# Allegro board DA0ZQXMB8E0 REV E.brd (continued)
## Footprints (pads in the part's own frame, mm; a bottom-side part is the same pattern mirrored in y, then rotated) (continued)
BGA1168-INTEL-HASWELL
  round 0.508 smd: A3(18.177,-11.314) A62(-18.722,-11.314) AW1(19.314,10.727) AY2(18.771,11.314) C1(19.314,-10.177)
  round 0.381 smd: A4(17.421,-11.314) AF9(14.282,3.12) AH28(2.793,3.975) AH42(-6.31,3.975) AH44(-7.611,3.975) AH46(-8.911,3.975) AJ43(-6.96,4.3) AJ45(-8.261,4.3) AJ47(-9.561,4.3) AT1(19.314,8.683) AU1(19.314,9.343) AV1(19.314,10.004) AV2(18.654,9.993) AW2(18.654,10.654) AW3(17.993,10.654) AY3(18.047,11.314) AY4(17.387,11.314) AY5(16.726,11.314) E23(5.981,-8.713) E25(4.6,-8.713) E27(3.474,-8.713) E43(-6.556,-8.713) E45(-7.937,-8.713) E47(-9.064,-8.713) E63(-19.314,-8.667) F1(19.314,-7.878) F22(6.597,-8.256) F24(5.291,-8.188) F26(4.037,-8.188) F28(2.783,-8.188) F42(-5.993,-8.188) F46(-8.5,-8.188) F48(-9.754,-8.188) G22(6.707,-7.546) G23(5.981,-7.863) G25(4.6,-7.863) G27(3.474,-7.863) G43(-6.556,-7.863) G45(-7.937,-7.863) G47(-9.064,-7.863) H22(6.707,-6.734) H23(6.199,-7.14) J22(6.707,-5.921) J23(6.199,-6.327)
  round 0.305 smd: A23(6.128,-11.314) A24(5.291,-10.989) A25(4.6,-11.314) A27(3.474,-11.314) A28(2.783,-10.989) A36(-2.232,-10.989) A44(-7.247,-10.989) A47(-9.064,-11.314) AA1(19.314,0.402) AA2(18.664,0.402) AA61(-18.014,0.324) AA62(-18.664,0.362) AA63(-19.314,0.362) AC1(19.314,1.152) AC2(18.664,1.152) AC61(-18.014,1.15) AC62(-18.664,1.112) AC63(-19.314,1.112) AD1(19.314,1.901) AD2(18.664,1.901) AD6(16.027,1.691) AD61(-18.014,1.823) AD62(-18.664,1.861) AD63(-19.314,1.861) AE5(16.678,2.643) AE7(15.377,2.643) AE8(14.727,2.643) AF1(19.314,2.65) AF2(18.664,2.65) AG1(19.314,3.4) AG2(18.664,3.4) AH1(19.314,4.149) AH2(18.664,4.149) AK2(18.664,4.898) AK61(-18.014,5.209) AK62(-18.664,5.315) AK63(-19.314,5.315) AL1(19.314,5.647) AL2(18.664,5.647) AL17(10.092,5.268) AL26(3.858,5.602) AL28(2.905,5.602) AL43(-6.582,5.602) AL45(-7.56,5.602) AL46(-8.487,5.602) AL48(-9.542,5.602) AM1(19.314,6.397) AM2(18.664,6.397) AM3(18.014,6.359) AM29(1.953,6.252) AM32(0.49,6.252) AM36(-2.266,6.252) AM38(-3.32,6.252) AM40(-4.817,6.252) AM42(-5.63,6.252) AM43(-6.582,6.252) AM45(-7.56,6.252) AM46(-8.487,6.252) AM48(-9.542,6.252) AM52(-12.269,6.252) AM54(-13.295,6.252) AN1(19.314,7.146) AN2(18.664,7.146) AN36(-2.266,6.903) AN38(-3.32,6.903) AN39(-4.228,6.578) AN40(-4.817,6.903) AN42(-5.63,6.903) AN43(-6.582,6.903) AN45(-7.56,6.903) AN46(-8.487,6.903) AP1(19.314,7.895) AP2(18.664,7.895) AP8(15.011,7.738) AP36(-2.266,7.553) AP38(-3.32,7.553) AP39(-4.228,7.228) AP45(-7.56,7.553) AR5(16.413,8.063) AR8(15.011,8.388) AR15(11.174,8.388) AR42(-5.63,8.203) AR45(-7.56,8.203) AR46(-8.487,8.203) AR48(-9.542,8.203) AT2(18.664,8.645) AT3(18.014,8.683) AT4(17.363,8.683) AT7(15.575,8.713) AT10(13.657,8.713) AT13(11.738,8.713) AT43(-7.422,8.905) AT46(-8.996,8.905) AU2(18.659,9.333) AU3(17.999,9.333) AU4(17.338,9.333) AU6(15.977,9.363) AU8(14.478,9.363) AU12(12.154,9.363) AU42(-6.309,9.363) AU43(-6.959,9.363) AU44(-7.884,9.363) AU46(-8.534,9.363) AU47(-9.459,9.363) AV3(17.993,9.993) AV4(17.338,9.993) AV5(16.65,10.014) AV6(15.977,10.014) AV7(15.151,10.014) AV8(14.478,10.014) AV10(13.653,10.014) AV11(12.98,10.014) AV42(-6.26,10.014) AV43(-7.009,10.014) AV44(-7.834,10.014) AW4(17.338,10.654) AW5(16.688,10.664) AW6(15.939,10.664) AW7(15.189,10.664) AW8(14.44,10.664) AW11(12.942,10.664) AW12(12.192,10.664) AW23(5.672,10.664) AW25(4.321,10.664) AW29(1.89,10.664) AW30(1.214,10.339) AW31(0.539,10.664) AW33(-0.137,10.339) AW34(-0.71,10.664) AW37(-3.11,10.664) AW39(-3.859,10.664) AW41(-5.434,10.664) AW42(-6.26,10.664) AW43(-7.009,10.664) AW49(-10.158,10.664) AW50(-10.984,10.664) AW51(-11.666,10.339) AW53(-13.017,10.339) AW54(-13.693,10.664) AY6(15.939,11.314) AY7(15.189,11.314) AY8(14.44,11.314) AY26(3.645,10.989) AY33(-0.137,10.989) AY40(-4.685,11.314) AY41(-5.434,11.314) AY49(-10.158,11.314) B23(5.864,-10.672) B24(5.291,-10.339) B25(4.6,-10.664) B26(4.037,-10.339) B27(3.474,-10.664) B28(2.783,-10.339) B37(-2.922,-10.664) B43(-6.556,-10.664) C21(7.423,-9.529) C24(5.263,-9.282) C25(4.6,-10.014) C26(4.037,-9.689) C27(3.474,-10.014) C28(2.756,-9.282) C31(0.966,-10.014) C33(-0.415,-10.014) C37(-2.922,-10.014) C39(-4.049,-10.014) C41(-5.43,-10.014) C42(-5.993,-9.689) C45(-7.937,-10.014) C46(-8.5,-9.689) C47(-9.064,-10.014) C48(-9.756,-9.282) D2(18.664,-9.24) D3(18.014,-9.278) D5(16.636,-9.472) D6(15.945,-9.529) D8(15.157,-9.529) D9(14.37,-9.529) D17(10.001,-9.529) D18(9.214,-9.529) D20(8.306,-9.529) D21(7.079,-8.891) D23(5.937,-9.529) D25(4.6,-9.363) D26(4.037,-9.038) D27(3.474,-9.363) D43(-6.556,-9.363) D47(-9.064,-9.363) E2(18.664,-8.589) E3(18.014,-8.627) E4(17.363,-8.627) E5(16.712,-8.695) E6(15.76,-8.695) E17(10.045,-8.695) E18(9.092,-8.695) E20(8.14,-8.695) F2(18.664,-7.84) F3(18.014,-7.802) F4(17.363,-7.802) F8(14.807,-8.045) F17(10.045,-8.045) F18(9.092,-8.045) F62(-18.664,-7.88) G3(18.014,-7.129) G4(17.363,-7.129) G5(16.712,-7.395) G6(15.76,-7.395) G8(14.807,-7.395) H5(16.712,-6.745) H6(15.76,-6.745) H8(14.807,-6.745) J3(18.014,-6.303) J4(17.363,-6.303) J5(16.687,-6.094) J6(15.747,-6.094) J8(14.807,-6.094) J11(12.902,-6.094) K1(19.314,-5.592) K2(18.664,-5.592) K61(-18.014,-5.67) K62(-18.664,-5.632) K63(-19.314,-5.632) L1(19.314,-4.843) L2(18.664,-4.843) L6(16.027,-4.977) L8(14.727,-4.977) L61(-18.014,-4.845) L62(-18.664,-4.883) L63(-19.314,-4.883) N1(19.314,-4.093) N2(18.664,-4.093) N3(18.014,-4.132) N4(17.363,-4.132) N5(16.678,-4.024) N6(16.027,-4.024) N7(15.377,-4.024) N8(14.727,-4.024) N61(-18.014,-4.172) N62(-18.664,-4.134) N63(-19.314,-4.134) P1(19.314,-3.344) P2(18.664,-3.344) P3(18.014,-3.306) P4(17.363,-3.306) P61(-18.014,-3.346) P62(-18.664,-3.384) P63(-19.314,-3.384) R5(16.678,-3.072) R6(16.027,-3.072) R7(15.377,-3.072) R8(14.727,-3.072) T1(19.314,-2.595) T2(18.664,-2.595) T3(18.014,-2.633) T4(17.363,-2.633) T61(-18.014,-2.673) T62(-18.664,-2.635) T63(-19.314,-2.635) U1(19.314,-1.846) U2(18.664,-1.846) U5(16.678,-2.119) U6(16.027,-2.119) U7(15.377,-2.119) U8(14.727,-2.119) U61(-18.014,-1.848) U62(-18.664,-1.886) U63(-19.314,-1.886) V1(19.314,-1.096) V2(18.664,-1.096) Y1(19.314,-0.347) Y2(18.664,-0.347) Y61(-18.014,-0.349) Y62(-18.664,-0.387) Y63(-19.314,-0.387)
  round 0.33 smd: AK23(5.786,4.952) AK25(4.81,4.952) AK26(3.858,4.952) AK28(2.905,4.952) AK43(-6.582,4.952) AK45(-7.56,4.952) AK46(-8.462,4.952) AK48(-9.516,4.952)
BSH-030-01-L-D-A-TR-60P-LDH
  round 1.016 hole 1.016 unplated: (-10.063,-2.666) (10.063,-2.666)
  rect 0.279x2.261 smd: 1(-7.25,-2.864) 2(-6.75,-2.864) 3(-6.25,-2.864) 4(-5.75,-2.864) 5(-5.25,-2.864) 6(-4.75,-2.864) 7(-4.25,-2.864) 8(-3.75,-2.864) 9(-3.25,-2.864) 10(-2.75,-2.864) 11(-2.25,-2.864) 12(-1.75,-2.864) 13(-1.25,-2.864) 14(-0.75,-2.864) 15(-0.25,-2.864) 16(0.25,-2.864) 17(0.75,-2.864) 18(1.25,-2.864) 19(1.75,-2.864) 20(2.25,-2.864) 21(2.75,-2.864) 22(3.25,-2.864) 23(3.75,-2.864) 24(4.25,-2.864) 25(4.75,-2.864) 26(5.25,-2.864) 27(5.75,-2.864) 28(6.25,-2.864) 29(6.75,-2.864) 30(7.25,-2.864) 31(7.25,2.864) 34(5.75,2.864) 36(4.75,2.864) 38(3.75,2.864) 39(3.25,2.864) 40(2.75,2.864) 41(2.25,2.864) 42(1.75,2.864) 43(1.25,2.864) 44(0.75,2.864) 45(0.25,2.864) 46(-0.25,2.864) 47(-0.75,2.864) 48(-1.25,2.864) 49(-1.75,2.864) 50(-2.25,2.864) 51(-2.75,2.864) 52(-3.25,2.864) 53(-3.75,2.864) 54(-4.25,2.864) 55(-4.75,2.864) 56(-5.25,2.864) 57(-5.75,2.864) 58(-6.25,2.864) 59(-6.75,2.864) 60(-7.25,2.864)
CC0402
  custom 0.12x0.12 smd: 1(0.39,0) 2(-0.39,0)
CC0603#2
  rect 0.813x0.711 smd: 1(0.737,0) 2(-0.737,0)
CC0805
  rect 0.94x1.346 smd: 2(-0.895,0)
CC1206
  rect 1.6x1.6 smd: 1(1.702,0) 2(-1.702,0)
CC1808
  rect 2.159x2.286 smd: 1(-2.349,0) 2(2.349,0)
CC3528
  rect 2.032x2.413 smd: 1(1.6,0) 2(-1.6,0)
CC7343
  rect 2.413x2.819 smd: 1(-3.2,0) 2(3.2,0)
CHOKE-PCMC063T-3R3MN-SMT#2
  rect 1.854x3.505 smd: 1(-3.275,0) 2(3.275,0)
CHOKE-PCMC063T-R82MN-4P-SMT
  custom 0.591x0.591 smd: 1(-3.596,0) 2(3.596,0)
  rect 1.473x0.305 smd: 3(-2.452,0) 4(2.452,0)
D-DO-214AC
  rect 1.88x2.032 smd: 1(-2.1,0)
DDR-C-2013289-204P
  round 1.6 hole 1.6 unplated: (-33.4,0)
  round 1.092 hole 1.092 unplated: (33.4,0)
  rect 0.356x2.007 smd: 1(-31.65,-4.1) 3(-31.05,-4.1) 4(-30.75,4.1) 5(-30.45,-4.1) 7(-29.85,-4.1) 8(-29.55,4.1) 9(-29.25,-4.1) 11(-28.65,-4.1) 13(-28.05,-4.1) 15(-27.45,-4.1) 17(-26.85,-4.1) 19(-26.25,-4.1) 21(-25.65,-4.1) 23(-25.05,-4.1) 31(-22.65,-4.1) 37(-20.85,-4.1) 41(-19.65,-4.1) 43(-19.05,-4.1) 49(-17.25,-4.1) 51(-16.65,-4.1) 53(-16.05,-4.1) 55(-15.45,-4.1) 59(-14.25,-4.1) 74(-7.35,4.1) 76(-6.75,4.1) 78(-6.15,4.1) 80(-5.55,4.1) 82(-4.95,4.1) 84(-4.35,4.1) 86(-3.75,4.1) 88(-3.15,4.1) 90(-2.55,4.1) 92(-1.95,4.1) 96(-0.75,4.1) 98(-0.15,4.1) 100(0.45,4.1) 102(1.05,4.1) 104(1.65,4.1) 106(2.25,4.1) 108(2.85,4.1) 110(3.45,4.1) 112(4.05,4.1) 114(4.65,4.1) 116(5.25,4.1) 118(5.85,4.1) 120(6.45,4.1) 122(7.05,4.1) 124(7.65,4.1) 126(8.25,4.1) 128(8.85,4.1) 130(9.45,4.1) 132(10.05,4.1) 134(10.65,4.1) 136(11.25,4.1) 138(11.85,4.1) 140(12.45,4.1) 142(13.05,4.1) 144(13.65,4.1) 148(14.85,4.1) 150(15.45,4.1) 152(16.05,4.1) 154(16.65,4.1) 156(17.25,4.1) 157(17.55,-4.1) 159(18.15,-4.1) 161(18.75,-4.1) 163(19.35,-4.1) 164(19.65,4.1) 165(19.95,-4.1) 166(20.25,4.1) 167(20.55,-4.1) 168(20.85,4.1) 171(21.75,-4.1) 173(22.35,-4.1) 175(22.95,-4.1) 176(23.25,4.1) 177(23.55,-4.1) 178(23.85,4.1) 179(24.15,-4.1) 181(24.75,-4.1) 183(25.35,-4.1) 184(25.65,4.1) 185(25.95,-4.1) 186(26.25,4.1) 187(26.55,-4.1) 189(27.15,-4.1) 191(27.75,-4.1) 193(28.35,-4.1) 195(28.95,-4.1) 196(29.25,4.1) 197(29.55,-4.1) 198(29.85,4.1) 199(30.15,-4.1) 200(30.45,4.1) 201(30.75,-4.1) 202(31.05,4.1) 203(31.35,-4.1) 204(31.65,4.1)
  rect 3.505x4.597 smd: 205(-32.8,12) 206(32.8,12)
DSM
  rect 1.016x0.508 smd: 1(-1.3,0) 2(1.321,0)
DSMV
  rect 1.016x0.762 smd: 1(-1.27,0) 2(1.27,0)
GS12401-1011-40P-R-NH-SMT
  round 0.94 hole 0.94 unplated: (-10.5,0) (10.5,0)
  rect 0.254x1.143 smd: 1(9.75,2.125) 2(9.25,2.125) 3(8.75,2.125) 4(8.25,2.125) 5(7.75,2.125) 6(7.25,2.125) 7(6.75,2.125) 8(6.25,2.125) 9(5.75,2.125) 10(5.25,2.125) 11(4.75,2.125) 12(4.25,2.125) 13(3.75,2.125) 14(3.25,2.125) 15(2.75,2.125) 23(-1.25,2.125) 24(-1.75,2.125) 25(-2.25,2.125) 27(-3.25,2.125) 28(-3.75,2.125) 29(-4.25,2.125) 30(-4.75,2.125) 31(-5.25,2.125) 32(-5.75,2.125) 33(-6.25,2.125) 34(-6.75,2.125) 35(-7.25,2.125) 36(-7.75,2.125) 37(-8.25,2.125) 38(-8.75,2.125) 39(-9.25,2.125) 40(-9.75,2.125)
  rect 1.499x2.997 smd: 41(12.65,0) 42(-12.65,0)
  rect 2.794x1.499 smd: 43(5.7,-2.45) 44(-5.7,-2.45)
H-C146D146N
  round 3.708 hole 3.708 unplated: (0,0)
HDMI-59075-01942-001-19P
  round 0.813 hole 0.559: 1(-4.5,6.65) 2(-4,8.2) 3(-3.5,6.65) 4(-3,8.2) 5(-2.5,6.65) 6(-2,8.2) 7(-1.5,6.65) 9(-0.5,6.65) 11(0.5,6.65) 13(1.5,6.65) 15(2.5,6.65) 17(3.5,6.65) 18(4,8.2) 19(4.5,6.65)
  oval 1.803x2.794 hole 0.787x1.803: 20(-9.25,0) 22(9.25,0)
  oval 1.803x3.607 hole 0.787x2.591: 21(-7.25,7.6) 23(7.25,7.6)
HG-C276D118P2
  round 7.01 hole 2.997: 1(0,0)
  round 1.016 hole 0.61: 2(0,2.502) 3(1.769,1.769) 4(2.502,0) 5(1.769,-1.769) 6(0,-2.502) 7(-1.769,-1.769) 8(-2.502,0) 9(-1.769,1.769)
HG-C315D118P2
  round 1.016 hole 0.61: 5(1.88,-1.88) 7(-1.88,-1.88)
HG-C315D146P2
  round 1.016 hole 0.61: 2(0,2.794) 3(1.976,1.976) 4(2.794,0) 5(1.976,-1.976) 6(0,-2.794) 7(-1.976,-1.976) 8(-2.794,0) 9(-1.976,1.976)
IMD
  rect 1.016x0.813 smd: 1(1.2,-1) 3(1.2,1)
L3_2X2_5-3_2
  rect 1.194x2.007 smd: 1(-1.6,0) 2(1.6,0)
LQFP128-16X16-4-1_6H
  rect 0.203x1.499 smd: 1(-6.2,-7.85) 2(-5.8,-7.85) 3(-5.4,-7.85) 4(-5,-7.85) 5(-4.6,-7.85) 6(-4.2,-7.85) 7(-3.8,-7.85) 8(-3.4,-7.85) 9(-3,-7.85) 10(-2.6,-7.85) 11(-2.2,-7.85) 68(5,7.85) 69(4.6,7.85) 70(4.2,7.85) 71(3.8,7.85)
  rect 1.499x0.203 smd: 100(-7.85,5) 101(-7.85,4.6) 125(-7.85,-5) 126(-7.85,-5.4) 127(-7.85,-5.8) 128(-7.85,-6.2)
MINICARD-110021-52131-52P-RUV
  rect 0.508x2.007 smd: 1(11.8,4.1) 2(11.4,-4.1) 3(11,4.1) 5(10.2,4.1) 7(9.4,4.1) 8(9,-4.1) 9(8.6,4.1) 10(8.2,-4.1) 12(7.4,-4.1) 14(6.6,-4.1) 16(5.8,-4.1) 18(1.8,-4.1) 19(1.4,4.1) 20(1,-4.1) 22(0.2,-4.1) 23(-0.2,4.1) 24(-0.6,-4.1) 25(-1,4.1) 26(-1.4,-4.1) 27(-1.8,4.1) 28(-2.2,-4.1) 29(-2.6,4.1) 30(-3,-4.1) 31(-3.4,4.1) 32(-3.8,-4.1) 33(-4.2,4.1) 34(-4.6,-4.1) 35(-5,4.1) 36(-5.4,-4.1) 37(-5.8,4.1) 38(-6.2,-4.1) 39(-6.6,4.1) 40(-7,-4.1) 41(-7.4,4.1) 42(-7.8,-4.1) 43(-8.2,4.1) 45(-9,4.1) 47(-9.8,4.1) 49(-10.6,4.1) 51(-11.4,4.1)
MSOP8-4_9-65
  rect 0.406x1.448 smd: 1(-0.975,-2.325) 2(-0.325,-2.325) 3(0.325,-2.325) 4(0.975,-2.325) 5(0.975,2.325) 6(0.325,2.325) 7(-0.325,2.325) 8(-0.975,2.325)
POWER-6_5-1_84-3P
  rect 0.787x1.397 smd: 2(3.532,-0.9)
PVQFN20-3_5X3_5-5-25P
  rect 0.279x0.838 smd: 1(-1,-1.725) 2(-0.5,-1.725) 12(0.5,1.725) 13(0,1.725) 14(-0.5,1.725)
  rect 0.838x0.279 smd: 6(1.725,-1) 7(1.725,-0.5) 8(1.725,0) 9(1.725,0.5) 17(-1.725,0.5) 18(-1.725,0)
QFN14-3X3-4-16P
  rect 1.092x0.203 smd: 1(-1.25,0.525) 2(-1.25,-0.175) 8(1.25,-0.525)
  rect 0.203x0.711 smd: 3(-0.8,-1.45) 4(-0.4,-1.45) 5(0,-1.45) 6(0.4,-1.45) 11(0.4,1.45) 12(0,1.45) 13(-0.4,1.45) 14(-0.8,1.45)
  rect 0.66x0.203 smd: 15(0,0.165) 16(0,-0.435)
QFN16-3X3-5-22P
  rect 0.305x0.991 smd: 1(-0.75,-1.6) 10(0.25,1.6) 11(-0.25,1.6) 12(-0.75,1.6)
  rect 0.991x0.305 smd: 7(1.6,0.25) 8(1.6,0.75) 14(-1.6,0.25) 15(-1.6,-0.25)
QFN20-3X3-4-26P
  rect 0.787x0.203 smd: 1(-1.5,0.8) 5(-1.5,-0.8) 11(1.5,-0.8) 12(1.5,-0.4) 13(1.5,0) 14(1.5,0.4) 15(1.5,0.8)
  rect 0.203x0.787 smd: 6(-0.8,-1.5) 7(-0.4,-1.5) 8(0,-1.5) 9(0.4,-1.5) 10(0.8,-1.5) 16(0.8,1.5) 19(-0.4,1.5) 20(-0.8,1.5)
  rect 1.803x1.803 smd: 21(0,0)
  round 0.508 hole 0.305: 22(-0.5,0.5) 23(-0.5,-0.5) 24(0.5,-0.5) 25(0.5,0.5) 26(0,0)
QFN32-4X4-4-33P-0_9H
  custom 0.051x0.051 smd: 1(-1.4,-2.1) 8(1.4,-2.1) 9(2.1,-1.4) 16(2.1,1.4) 17(1.4,2.1) 24(-1.4,2.1) 25(-2.1,1.4) 32(-2.1,-1.4)
  rect 0.203x0.991 smd: 2(-1,-2.1) 3(-0.6,-2.1) 4(-0.2,-2.1) 5(0.2,-2.1) 6(0.6,-2.1) 7(1,-2.1) 18(1,2.1) 19(0.6,2.1)
  rect 0.991x0.203 smd: 10(2.1,-1) 12(2.1,-0.2) 14(2.1,0.6) 15(2.1,1) 26(-2.1,1) 28(-2.1,0.2) 29(-2.1,-0.2) 30(-2.1,-0.6) 31(-2.1,-1)
  rect 2.692x2.692 smd: 33(0,0)
QFN32-4X4-4-42P-1H
  custom 0.05x0.05 smd: 2(-2,1) 3(-2,0.6) 8(-2,-1.4) 9(-1.4,-2) 10(-1,-2) 11(-0.6,-2) 17(2,-1.4) 18(2,-1) 19(2,-0.6) 20(2,-0.2) 21(2,0.2) 22(2,0.6) 23(2,1) 24(2,1.4) 25(1.4,2) 28(0.2,2) 30(-0.6,2) 31(-1,2) 32(-1.4,2)
  rect 2.794x2.794 smd: 33(0,0)
  round 0.61 hole 0.305: 34(-1,1) 35(-1,0) 37(0,-1) 38(1,-1) 40(1,1) 41(0,1) 42(0,0)
QFN48-6X6-4-49P-ALC280
  rect 0.203x0.991 smd: 1(-2.2,-3.1) 2(-1.8,-3.1) 3(-1.4,-3.1) 4(-1,-3.1) 5(-0.6,-3.1) 6(-0.2,-3.1) 7(0.2,-3.1) 8(0.6,-3.1) 9(1,-3.1) 10(1.4,-3.1) 11(1.8,-3.1) 12(2.2,-3.1) 25(2.2,3.1) 26(1.8,3.1) 27(1.4,3.1) 28(1,3.1) 29(0.6,3.1) 30(0.2,3.1) 31(-0.2,3.1) 32(-0.6,3.1) 33(-1,3.1) 34(-1.4,3.1) 35(-1.8,3.1) 36(-2.2,3.1)
  rect 0.991x0.203 smd: 13(3.1,-2.2) 14(3.1,-1.8) 15(3.1,-1.4) 16(3.1,-1) 17(3.1,-0.6) 18(3.1,-0.2) 19(3.1,0.2) 20(3.1,0.6) 21(3.1,1) 22(3.1,1.4) 23(3.1,1.8) 24(3.1,2.2) 37(-3.1,2.2) 38(-3.1,1.8) 39(-3.1,1.4) 40(-3.1,1) 41(-3.1,0.6) 42(-3.1,0.2) 43(-3.1,-0.2) 44(-3.1,-0.6) 45(-3.1,-1) 46(-3.1,-1.4) 47(-3.1,-1.8) 48(-3.1,-2.2)
  rect 4.394x4.394 smd: 49(0,0)
RC0402
  custom 0.12x0.12 smd: 1(0.39,0) 2(-0.39,0)
RC0402#3
  custom 0.12x0.12 smd: 2(-0.39,0)
RC0603
  rect 0.813x0.711 smd: 1(0.737,0) 2(-0.737,0)
RC0603#3
  rect 0.813x0.711 smd: 2(-0.737,0)
RC0805
  rect 0.94x1.346 smd: 1(0.895,0) 2(-0.895,0)
RC1206
  rect 1.6x1.6 smd: 1(1.702,0) 2(-1.702,0)
RC3216
  rect 3.2x0.94 smd: 1(0,0.825) 2(0,-0.825)
RJ45-JM361C-HP34AA03-9H-8P
  round 1.295 hole 0.889: 1(3.57,10.1) 2(2.55,11.2) 3(1.53,10.1) 4(0.51,11.2) 5(-0.51,10.1) 6(-1.53,11.2) 7(-2.55,10.1) 8(-3.57,11.2)
  oval 1.092x2.108 hole 0.61x1.6: 9(8.4,0) 10(8.4,7.8) 11(-8.4,0) 12(-8.4,7.8)
SC70-2_1-65-6P
  rect 1.27x0.279 smd: 1(1.02,-0.65) 2(1.02,0) 3(1.02,0.65) 4(-1.02,0.65) 5(-1.02,0) 6(-1.02,-0.65)
SC70-2_1-65-6P#2
  rect 1.27x0.279 smd: 1(1.02,-0.65)
SHORT0402#2
  rect 0.648x0.5 smd: 1(-0.39,0) 2(0.39,0)
SHORT0402#3
  rect 0.648x0.5 smd: 1(-0.39,0)
SHORT0805
  rect 1.397x1.346 smd: 1(0.895,0) 2(-0.895,0)
SHORT0805#3
  rect 1.397x1.346 smd: 2(-0.895,0)
SHORT3720
  rect 3.759x1.537 smd: 1(0,1.008) 2(0,-1.008)
SHORT3720#3
  rect 3.759x1.537 smd: 2(0,-1.008)
SO-8FL-5P-OA
  rect 0.991x0.762 smd: 1(3.73,-1.905) 2(3.73,-0.635) 3(3.73,0.635) 4(3.73,1.905)
  custom 1.132x1.132 smd: 5(0,0)
SOIC8-6-1_27
  rect 0.533x1.753 smd: 4(1.905,-2.73) 6(0.635,2.73)
SOIC8-8-1_27
  rect 0.533x1.6 smd: 1(1.905,3.8) 2(0.635,3.8) 3(-0.635,3.8) 4(-1.905,3.8) 5(-1.905,-3.8) 6(-0.635,-3.8) 7(0.635,-3.8) 8(1.905,-3.8)
SOT23-2_8-95-6P
  rect 1.346x0.508 smd: 1(1.325,-0.95) 2(1.325,0) 3(1.325,0.95) 4(-1.325,0.95) 5(-1.325,0) 6(-1.325,-0.95)
SOT23-5
  rect 1.016x0.711 smd: 1(1.2,-0.95) 2(1.2,0) 3(1.2,0.95) 4(-1.2,0.95) 5(-1.2,-0.95)
SOT23-6-2_8-95-6P
  rect 1.194x0.508 smd: 1(1.5,-0.95) 5(-1.5,0) 6(-1.5,-0.95)
SOT23_123-2_8-1_9
  rect 1.092x0.533 smd: 1(1.45,-0.95) 2(1.45,0.95) 3(-1.45,0)
SOT23_213-3_3-2
  rect 1.27x1.016 smd: 1(1.016,1.016) 2(1.016,-1.016) 3(-1.016,0)
SOT353-1-2_125-65-5P
  rect 1.245x0.279 smd: 1(1.045,-0.65) 2(1.045,0) 5(-1.045,-0.65)
SSOP5-P-A-TOSHIBA-B
  rect 1.067x0.305 smd: 1(0.85,-0.65) 2(0.85,0) 3(0.85,0.65) 4(-0.85,0.65) 5(-0.85,-0.65)
SW-TME-532-V-6P
  rect 1.803x1.092 smd: 2(3.1,1.85) 3(-3.1,-1.85)
TP2650
  round 0.66 smd: 1(0,0)
TP2675
  round 0.66 smd: 1(0,0)
TRF-9_4-1_27-24P
  rect 0.762x1.219 smd: 1(-6.985,-4.35) 2(-5.715,-4.35) 3(-4.445,-4.35) 4(-3.175,-4.35) 10(4.445,-4.35) 11(5.715,-4.35) 12(6.985,-4.35) 15(4.445,4.35) 16(3.175,4.35) 17(1.905,4.35) 18(0.635,4.35) 19(-0.635,4.35) 20(-1.905,4.35) 21(-3.175,4.35) 22(-4.445,4.35) 23(-5.715,4.35) 24(-6.985,4.35)
TSOP6-2_8-95
  rect 0.787x0.635 smd: 1(1.2,-0.95) 2(1.2,0) 3(1.2,0.95)
TSSOP28-6_4-65-SLB9635TT
  rect 0.406x1.295 smd: 1(-4.225,-3.05) 2(-3.575,-3.05) 3(-2.925,-3.05) 4(-2.275,-3.05) 6(-0.975,-3.05) 7(-0.325,-3.05) 8(0.325,-3.05) 9(0.975,-3.05) 10(1.625,-3.05) 11(2.275,-3.05) 12(2.925,-3.05) 13(3.575,-3.05) 14(4.225,-3.05) 15(4.225,3.05) 16(3.575,3.05) 17(2.925,3.05) 18(2.275,3.05) 19(1.625,3.05) 20(0.975,3.05) 21(0.325,3.05) 22(-0.325,3.05) 23(-0.975,3.05) 24(-1.625,3.05) 25(-2.275,3.05) 26(-2.925,3.05) 27(-3.575,3.05) 28(-4.225,3.05)
UMT_213-3-1_3
  rect 1.016x0.762 smd: 1(0.991,0.66) 2(0.991,-0.66) 3(-0.991,0)
VQFN14-3_5X3_5-5-15P
  rect 0.279x0.838 smd: 4(0,-1.725) 5(0.5,-1.725) 6(1,-1.725) 10(0.5,1.725)
  rect 0.838x0.279 smd: 8(1.725,0.75) 14(-1.725,0.75)
  rect 2.057x2.057 smd: 15(0,0)
WDFN5-3_05X3_05-65
  rect 0.66x0.432 smd: 1(1.385,-0.975) 3(1.385,0.325) 4(1.385,0.975)
  custom 0.575x0.575 smd: 5(-0.735,0)
XTAL-8_4X3_7-5_5X2_8
  rect 1.295x2.057 smd: 1(-2.75,-1.425) 2(2.75,-1.425) 3(2.75,1.425) 4(-2.75,1.425)
XTL-3_2X2_5-2_2X1_7
  rect 1.397x1.194 smd: 1(-1.1,-0.85) 2(1.1,-0.85) 3(1.1,0.85) 4(-1.1,0.85)
XTL-3_2X2_5-2_2X1_7-0_8H
  rect 1.397x1.194 smd: 1(-1.1,-0.85) 2(1.1,-0.85) 3(1.1,0.85) 4(-1.1,0.85)

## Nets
1.5V_VSNS: PR134.2 PR137.1
3V_MAIN_PWGD: PR8.2 R386.2 R401.1
3VPCU_VIN: PC112.2 PR21.1 PU10.1
5VPCU_AGND: PC63.1 PC181.1 PR129.2 PU16.14
51211V_TRIP: PR173.2
51211V_TST: PR175.2
+1.05V_DCPSUS1: C231.1 R237.2
+1.05V_DCPSUS2: C232.1 R238.1
+1.05V_DCPSUS4: C230.1 R236.2
+1.5VA: C301.1 C302.1 R252.1 U17.40
+1V_SRC: JP13.1 PC128.2 PL10.2 PR37.1
+3V_EC: C419.1 R414.1 U25.11
+3V_MAIN: R376.1 R381.2
+3V_PCH_ME: C420.2 R416.1 R418.2 R419.1 U24.8
+3V_RTC: C170.2 C171.2 C412.1 C436.1 C447.1 D29.3 R481.1 R513.2 R517.1 R524.1 R526.1 U25.3
+3V_RTC_1: D29.1 R509.2
+3V_RTC_2: D29.2
+3VCC_S5: C202.2 C203.1 Q20.3 TP23.1
+A3VPCU: C424.1 L17.2
+V1.05S_AIDLE: C176.1 U28.N8
+V1.05S_APLLOPI: C184.2 C196.2 C206.1 L9.2
+V1.05S_ASATA3PLL: C454.2 C455.2 C457.1 L18.2 R538.1 R539.2
+V1.05S_AXCK_DCB: C179.2 C180.2 C188.1 L10.2
+V1.05S_AXCK_LCPLL: C460.2 C461.2 C462.1 L19.2 R546.1
+V1.05S_VCCUSBCORE: C229.1 R230.2
+V3.3DX_1.5DX_1.8DX_AUDIO: C189.2
+V3.3M_PSPI: C192.2 R522.2
+V3.3S_VCCPCORE: C446.2 R523.1
+V3.3S_VCCPTS: C208.1
+VCCIOA_OUT: R229.2 U28.E20
+VCCPDSW: C163.1 C181.2 R171.1
+VCCRTCEXT: C193.2 U28.AE7
+VIN_VCCIN: JP16.1 PC39.2 PC40.2 PC45.2 PC48.2 PC147.2 PC150.2 PC160.2 PC161.2 PR87.1 PR88.1
AGND_DDR: PC33.2 PC34.2 PC36.2 PR71.1 PR72.1 PR189.2 PU6.7 PU6.21 PU6.22 PU6.23 PU6.24 PU6.25 PU6.26
DVDD_IO: C330.1 C331.1 R292.1 R294.1 U17.9
VCC_SENSE_R: R566.2 R582.1 U28.E63
VCCST_PWRGD_EN: R604.2 R612.1 R613.1 U37.2
VCCST_PWRGD_R: R588.1
VCCST_PWRGD_XDP: CN6.50 R620.2
VDD10: C306.1 C319.2 C324.2 C325.1 C328.1 C329.1 C336.1 C570.1 L20.2 U36.3 U36.8 U36.30
VDDREG/VDD33: C309.2 C551.2 R585.2
VSS_SENSE: PC43.1 PR97.2 R581.2
VSS_SENSE_R: R567.1 R581.1
670PG: PU10.4
671_BST: PR216.1
671_BST1: PC175.1 PR216.2
671_EN: PC63.2 PR225.1 PR228.2 PU16.13
671_FB: PR126.2 PR129.1 PU16.12
671_SW: PC175.2 PL14.1 PR123.1 PU16.8 PU16.15 PU16.16
671PG: PU16.4
1658R-COMP: PC115.1 PC116.1
1658R-EN: PR156.2
1658R-PVCC: PC9.1
1658R-REFIN: PC103.2 PR15.2 PR17.1
1658R-UGATE1: PQ34.4
24707_LX: PC184.1 PL15.2 PQ50.5 PQ51.1 PQ51.3 PR122.1
24737_ACDET: PR127.2 PR131.2 PU17.6
24737_ACN: PC65.1 PC192.2 PU17.1
24737_BM#: PQ31.2 PR213.1
24737_BST: PU17.17
24737_CMPIN: PR135.2 PR230.2 PR231.1
24737_CMPOUT: PQ33.2 PR231.2 PR232.1
24737_DH: PQ51.4 PU17.18
24737_DL: PQ50.4
24737_ILIM: PC173.2 PR214.2 PR215.2 PR218.1
24737_REGN: PC177.1 PD13.2
24737_SRN: PC54.1 PC171.2 PR210.1
24737_SRP: PC54.2 PC58.2 PR212.1
24737_VCC: PC188.2 PR136.2
51216_MODE: PR72.2 PU6.19
51216_REFIN: PC33.1 PR68.2 PR189.1 PU6.8
51216_S3: PR69.2 PR188.2
51216_S5: PR188.1 PU6.16
51216_TRIP: PR71.2
51624_ALERT#: PR108.2 PU7.32
51624_B-RAMP: PR79.2 PR85.1 PU7.11
51624_CLK: PR107.2 PU7.31
51624_COMP: PC50.2 PR106.2 PR111.2 PR112.1
51624_CSN1: PC152.2 PC153.1 PR192.1 PR201.2 PU7.18
51624_CSN2: PC155.1 PC156.2 PR93.2 PR95.1 PR195.1 PR204.2 PU7.19
51624_CSP1: PC151.1 PC152.1 PR74.2 PR191.1 PR201.1 PU7.17
51624_CSP2: PC156.1 PC157.1 PR92.2 PR98.1 PR194.1 PR204.1 PU7.20
51624_DATA: PR109.2
51624_DROOP: PC46.1 PC50.1 PR111.1 PU7.25
51624_F-IMAX: PR78.2 PR86.1 PU7.10
51624_GFB: PR100.1 PU7.23
51624_IMON: PC41.1 PR90.1
51624_MODE: PR101.2
51624_O-USR: PR77.2 PR84.1 PU7.9
51624_OCP-I: PR81.1 PR89.2 PR90.2
51624_PWM2: PR99.1
51624_SLEWA: PR199.1 PR200.2
51624_THERM: PC149.1 PR198.2 PR203.1
51624_V5A: PC159.1 PR110.1 PU7.28
51624_VBAT: PR88.2
51624_VDD: PC47.1 PR105.1 PU7.2
51624_VFB: PR102.1 PU7.24
51624_VREF: PC158.1 PR77.1 PR78.1 PR79.1 PR106.1 PR200.1 PR203.2
51624_VRON: PR83.2 PR91.1 PR94.2 PU7.8
+AZA_VDD: C299.1 C300.1 C307.1 R256.1 U17.1 U17.36
+PCH_VCCDSW: C181.1 C195.1
+SMDDR_VREF_DIMM: C162.1 C175.1 C177.1 C226.1 C234.1 C308.1 C464.1 C466.1 C525.2 C527.1 C555.1 JDIM6.126 R275.1 R280.2 R281.2 U12.M8 U13.M8 U14.M8 U15.M8 U26.M8 U27.M8 U29.M8 U32.M8
+SMDDR_VREF_DQ0: C224.1 C239.1 C279.1 C281.2 C312.1 C326.1 C432.1 C449.1 C451.1 R283.2 R288.2 R290.1
+SMDDR_VREF_DQ1: C332.1 C333.2 C334.1 JDIM6.1 R285.2 R286.1 R295.2
+VGPU_CORE: PC17.1 PC90.1 PC119.1 PC123.1
A_LAD0_R: CN8.8
A_LAD1_R: CN8.10
A_LAD2_R: CN8.12
A_LAD3_R: CN8.14 R63.2
A_LFRAME#_R: CN8.16 R60.2
ACIN: PQ53.3 PR233.1
ACPRESENT: PR227.1 R139.2
ACZ_SDIN: R287.2 U17.8
APWROK_R: R605.2 R614.1 R615.2
BEEP_1: C338.1 C339.2 R299.1 R300.2
BL#: Q10.2 Q10.3 R65.1
BOARD_ID0: R463.2 R492.1 U28.P1
BOARD_ID1: R156.2 R181.1 U28.R5
BOARD_ID2: R154.2 R178.1
BOARD_ID3: R533.2 R534.1
BOARD_ID4: R461.2 R489.1
CATERR#: TP49.1 U28.K61
CCD_PWR: C10.2 C13.2 CN7.32 CN7.33
CFG2: CN6.38 U28.AC63
CFG4: CN6.44 R255.1
CFG5: CN6.45 U28.Y62
CFG6: CN6.47 U28.Y61
CFG7: CN6.48
CFG10: CN6.23 R308.1
CFG11: CN6.22
CFG12: CN6.17 U28.T63
CFG13: CN6.16 U28.T62
CFG14: CN6.14 U28.T61
CFG15: CN6.13
CFG_RCOMP: R254.2
CK_XDP_P_R: CN6.11 R548.1
CL_CLK: TP98.1 U28.AF2
CL_DAT: TP96.1 U28.AD2
CL_RST1#_WLAN: CN8.49 TP74.1
CL_RST#: TP97.1
CLK_PCH_PCI3: R227.2 R228.2
CLK_PCH_PCI4: R225.2
CLK_PCI_LPC: C210.2 R9.1 R227.1
CLK_PCIE_LAN_REQ#: Q25.3 R450.2 R622.2
CLK_PCIE_LANN: U28.C41 U36.16
CLK_PCIE_LANP: U36.15
CLK_PCIE_N0: TP108.1
CLK_PCIE_P0: TP106.1 U28.C42
CLK_PCIE_REQ0#: R474.2 TP92.1 U28.U2
CLK_PCIE_REQ1#: R143.2 TP22.1
CLK_PCIE_REQ2#: R450.1 R451.2 U28.AD1
CLK_PCIE_REQ3#: R462.1 R490.2 U28.N1
CLK_PCIE_REQ4#: R125.1 R158.1 R183.1 U28.U5
CLK_PCIE_REQ5#: R477.2 U28.T2
CLK_PCIE_WLANP: U28.C37
CLK_PCIE_XDPN: R547.2
CLK_PCIE_XDPP: R548.2
CLK_PEGA_REQ#: Q12.3 R83.2 R125.2
CLK_SCLK: CN6.57 JDIM6.202 Q17.1 R11.1 R117.1 R133.1
CLKRUN#: R160.1
CODEC_VREF: C340.2 U17.28
CPU_DRAMRST#: R217.2 R220.2
CS_BST1: PC148.1
CS_BST2: PC165.1
CS_BSTR1: PR197.2
CS_BSTR2: PR207.2
CS_SW2: PL13.1 PR96.1
DDR_PG_CTRL: R572.1
DDR_VTTREF: PC36.1 PU6.5
DDR_VTTT_PG_CTRL: Q41.2 R573.2
DEVSLP1: R460.1 TP93.1 U28.L2
DGPU_D1: PC24.2 PQ20.2 PQ22.3 PR54.2
DGPU_HOLD_RST#: R496.2
DGPU_OTP#: Q9.3
DGPU_PSI: PR6.1 PR9.1 PR12.1
DGPU_PW_CTRL#: R464.1 R493.2 U28.P3
DGPU_PWROK: R494.1 U28.T3
DGPU_SELECT#: R488.1 U28.L1
DIMM1_SA0: JDIM6.197 R456.1
DIMM1_SA1: JDIM6.201 R446.1
DNBSWON#: R128.2
DP_UTIL: R551.2 R552.2
DPWROK_R: R478.1 R479.1 R482.1 U28.AV5
DSWVREN: R513.1 R514.2 U28.AW7
E51_TXD: TP81.1
EC_FPBACK#: Q8.2
EC_PECR_R: R392.1
EC_PWROK: R606.2 R608.1 R616.2 U38.2
EC_PWROK_R: R518.1 R601.2 U28.AY7
ECAGND: C423.1 C424.2 L16.2
EDP_AUX#_C: C21.2 R42.1 R370.2
EDP_AUX_C: C16.2 CN7.23 R38.1 R369.2
EDP_RCOMP: R229.1 U28.D20
EDP_TX0#_C: C394.2
EDP_TX0_C: C393.2
EDP_TX1#_C: C392.2
EDP_TX1_C: C391.2
EDP_TXP0: C393.1
EDP_VDD_EN_R: R78.2 U6.3
FAN1_PWM: Q16.1
FAN2SIG: TP15.1
FAN_PWM_CN1: Q16.3 R102.2
FANSIG: R103.2
GPIO15: R161.2 R186.1 U28.AD6
GPIO24: R187.1 TP21.1
GPIO25: R147.1 TP25.1
GPIO28: R162.1 TP29.1
GPIO37: R498.1 U28.AC1
GPIO44: R166.1 TP30.1
GPIO45: R138.1 R164.1
GPIO47: R144.1 TP26.1
GPIO56: R189.1 TP27.1
GPIO58: R190.1 TP19.1
GPIO59: R211.1 TP34.1
GPIO64: R201.1 U28.E3
GPIO65: R205.1 U28.F4
GPIO66: R520.2 R527.1 U28.D3
GPIO67: R206.1 U28.E4
GPIO68: R531.1
GPIO69: R515.1 U28.E2
GPIO84: R176.1 U28.L6
GPIO85: R180.1 U28.N6
GPIO86: R200.1 R202.2 U28.L8
GPIO88: R152.1
GPIO89: R140.1 U28.N7
GPIO90: R459.1 U28.K2
GPIO91: R454.1
GPIO92: R153.1
GPIO93: R487.1
GPIO94: R486.1
GPP_TX2N_LAN: C574.1 U36.18
GPP_TX2P_LAN: C575.1 U36.17
H_CPU_SVIDART#: R263.1 U28.L62
H_CPU_SVIDCLK: R268.2 U28.N63
H_CPU_SVIDDAT: R258.2 R259.2 R260.2 U28.L63
H_PECI: R392.2 U28.N62
H_PROCHOT#: PQ33.3 PR138.1 PR206.2 PU7.30 Q18.3 R569.1 R578.1 R579.1
H_PROCHOT#_R: R569.2 U28.K63
H_PWRGOOD_R: R565.1
HDA_BCLK_R: R529.2 U28.AW8
HDA_RST#_R: R530.2 U28.AU8
HDA_SDO_R: R535.1 R536.2
HDA_SYNC_R: C450.2 R532.2 U28.AV11
HDMI_5V: C356.1 CN18.18 D20.2 Q27.1
HDMI_DDCCLK_COM: Q24.1 R307.1 R314.1
HDMI_DDCCLK_MB: CN18.15 Q24.3 R321.1
HDMI_DDCCLK_SW: R314.2
HDMI_DDCDATA_COM: Q28.1 R317.1 R319.1
HDMI_DDCDATA_MB: Q28.3 R323.1
HDMI_MB_HP: Q23.3 R305.2 R306.1
HP_DET_CN: CN18.19 R305.1 RV6.1
HP_JD#: CN11.21 R304.2
HPL: R630.1 U17.32
HPL_C: C355.1 CN11.23 R629.1 R630.2
HPR: R631.1 U17.33
HWPG: D9.2 D10.2 D11.2 D12.2 D13.2 R87.1
HWPG_1.5V: D12.1 PR130.1 PU8.14
HWPG_1.05V_S5: D10.1 PR172.1 R612.2 R620.1
I2C1_SCL_GPIO7: Q6.4 Q44.4 R46.2 R512.1 R634.2 U28.F1
I2C1_SCL_GPIO7_CONN: CN7.8 Q6.3 R39.2 R46.1
I2C1_SDA_GPIO6: Q6.1 Q44.1 R47.2 R483.1 R626.2 U28.G4
I2C_TP_SCL_R: Q44.3 R634.1 R635.1
I2C_TP_SDA_R: Q44.6 R625.1 R626.1
ICLK_BIAS: R546.2 U28.C26
ICMNT: C423.2 PC186.2 PR135.1 PU17.7
IMVP_PWRGD_3V: Q43.2 R607.2 R623.2 U38.1
INT_AMIC-VREFO: C349.1 R309.2 U17.27
INT_HDMI_HPD: Q23.1 R301.2
INT_HDMICLK+: C362.1
INT_HDMICLK+_C: C362.2 R324.1 R637.1
INT_HDMICLK-: C361.1
INT_HDMICLK-_C: C361.2 R324.2 R636.1
INT_HDMITX0N: C365.1
INT_HDMITX0N_C: C365.2 CN18.9 R326.2 R640.1
INT_HDMITX0P: C366.1
INT_HDMITX0P_C: C366.2 CN18.7 R326.1 R641.1
INT_HDMITX1N: C363.1
INT_HDMITX1N_C: C363.2 CN18.6 R325.2 R638.1
INT_HDMITX1P: C364.1
INT_HDMITX1P_C: C364.2 CN18.4 R325.1 R639.1
INT_HDMITX2N: C367.1
INT_HDMITX2N_C: C367.2 CN18.3 R327.2 R642.1
INT_HDMITX2P: C368.1
INT_HDMITX2P_C: C368.2 CN18.1 R327.1 R643.1
IRQ_SERIRQ: R100.1 R182.1 U25.5 U28.T4
ISOLATEB: R293.2 R597.1
L_SPK-_1: C566.1 CN15.4
LAN_MX0+: CN12.1
LAN_MX0-: CN12.2
LAN_MX1+: CN12.3 U30.18
LAN_MX1-: CN12.6 U30.17
LAN_MX2+: CN12.4 U30.20
LAN_MX2-: CN12.5 U30.19
LAN_MX3+: CN12.7 U30.24
LAN_MX3-: CN12.8 U30.23
LANCT3: C283.1 R241.1
LCDVCC: C17.1 C18.2 C31.2 C32.2 C33.1 C81.2 CN7.34 CN7.35 CN7.36 U6.1
LGND: C283.2 CN12.9 CN12.10 HOLE12.5 HOLE12.7 R241.2
LINE1L-VREFO: R629.2 U17.31
LINE1L_R: C355.2 U17.22
LINE1R_R: C354.2 U17.21
LM393_PIN2: PR179.2 PR180.2
LPC_LAD1: U8.23 U25.9 U28.AW12
LPC_LAD2: U8.20 U25.8
LPC_LAD3: R63.1 U8.17 U25.7 U28.AW11
LPCPD#: R650.1
M_A_A0: R114.2
M_A_A1: R441.2
M_A_A8: R480.2 U12.T8 U13.T8 U14.T8 U15.T8 U26.T8 U27.T8 U29.T8 U32.T8
M_A_A11: R118.2 U28.AW41
M_A_A15: R436.2 U12.M7 U13.M7 U14.M7 U15.M7 U26.M7 U27.M7 U28.AU42 U29.M7 U32.M7
M_A_CLK1: C552.1 R431.2
M_A_CLK1#: C552.2 R432.2 U26.K7 U27.K7 U29.K7 U32.K7
M_A_DQ6: U28.AK61
M_A_DQ9: U15.A2 U32.A7
M_A_DQ15: U15.A7 U32.A3
M_A_DQ24: U14.A3
M_A_DQ25: U28.AW54
M_A_DQ28: U14.A2 U29.A7
M_A_DQ30: U14.A7 U29.A3
M_A_DQ31: U29.A2
M_A_DQ32: U13.A3 U27.A7
M_A_DQ33: U28.AW31
M_A_DQ35: U13.A7 U27.A3 U28.AW29
M_A_DQ36: U13.A2
M_A_DQ39: U27.A2
M_A_DQ43: U28.AW25
M_A_DQ48: U12.A2
M_A_DQ49: U28.AW23
M_A_DQ52: U12.A3 U26.A7
M_A_DQ55: U26.A2
M_A_DQS#4: U28.AW30
M_A_ZQ1: R242.2 U15.L8
M_A_ZQ2: R234.2 U14.L8
M_A_ZQ3: R213.2 U13.L8
M_A_ZQ4: R113.2 U12.L8
M_A_ZQ5: R586.2 U32.L8
M_A_ZQ6: R553.2 U29.L8
M_A_ZQ7: R543.2 U27.L8
M_A_ZQ8: R528.2 U26.L8
M_B_A0: JDIM6.98
M_B_A2: JDIM6.96
M_B_A3: U28.AR42
M_B_A4: JDIM6.92 U28.AR45
M_B_A5: U28.AP45
M_B_A6: JDIM6.90
M_B_A7: JDIM6.86
M_B_A9: U28.AU46
M_B_A11: JDIM6.84
M_B_A12: U28.AU47
M_B_A14: JDIM6.80 U28.AR46
M_B_A15: JDIM6.78
M_B_BS#1: JDIM6.108 U28.AM36
M_B_CKE0: U28.AY49
M_B_CKE1: JDIM6.74
M_B_CLK0: U28.AN38
M_B_CLK0#: U28.AM38
M_B_CLK1: JDIM6.102
M_B_CLK1#: JDIM6.104
M_B_CS#0: JDIM6.114 U28.AM32
M_B_DQ2: JDIM6.21
M_B_DQ3: JDIM6.23
M_B_DQ10: JDIM6.51 U28.AM54
M_B_DQ12: JDIM6.41
M_B_DQ15: JDIM6.53
M_B_DQ16: JDIM6.7
M_B_DQ17: JDIM6.5
M_B_DQ18: JDIM6.17 U28.AM43
M_B_DQ19: U28.AM45
M_B_DQ20: U28.AK45
M_B_DQ21: JDIM6.15 U28.AK43
M_B_DQ22: U28.AM40
M_B_DQ23: JDIM6.4 U28.AM42
M_B_DQ24: U28.AM46
M_B_DQ25: U28.AK46
M_B_DQ28: U28.AM48
M_B_DQ29: U28.AK48
M_B_DQ31: JDIM6.59
M_B_DQ32: JDIM6.130 U28.AM29
M_B_DQ33: JDIM6.132
M_B_DQ34: U28.AL28
M_B_DQ35: U28.AK28
M_B_DQ36: JDIM6.140
M_B_DQ37: JDIM6.142
M_B_DQ42: JDIM6.159
M_B_DQ44: U28.AK26
M_B_DQ45: JDIM6.148
M_B_DQ46: JDIM6.157 U28.AK25
M_B_DQ48: JDIM6.177
M_B_DQ49: JDIM6.166
M_B_DQ51: JDIM6.163
M_B_DQ52: JDIM6.164
M_B_DQ53: JDIM6.175
M_B_DQ54: JDIM6.176
M_B_DQ55: JDIM6.165
M_B_DQ56: JDIM6.183
M_B_DQ57: JDIM6.181
M_B_DQ58: JDIM6.191
M_B_DQ59: JDIM6.193
M_B_DQS5: JDIM6.154
M_B_DQS6: JDIM6.171
M_B_DQS#2: U28.AL43
M_B_DQS#3: U28.AL48
M_B_DQS#5: JDIM6.152
M_B_DQS#7: JDIM6.186
M_B_ODT0: TP45.1
M_B_ODT0_DIMM: JDIM6.116 R544.2
M_B_ODT1_DIMM: JDIM6.120 R542.2
M_B_RAS#: JDIM6.110
MAINON_ON_G: PQ6.3 PQ7.2 PQ16.2 PQ27.2 PQ38.2 PR38.1 PR39.2
MDI_0+: U30.11 U34.1 U36.1
MDI_0-: U30.12 U36.2
MDI_1+: U36.4
MDI_1-: U34.3 U36.5
MDI_2+: U35.1 U36.6
MDI_2-: U36.7
MDI_3+: U30.1 U36.9
MDI_3-: U30.2 U35.3 U36.10
ME_WR#: R535.2
MIC2-VREFO: CN11.27 R297.2 U17.29
MODPHY_D: PC27.2 PQ15.3 PQ23.2 PR58.2
MX0: C569.2 CN14.1 RP7.1
MX1: C572.2 CN14.2 RP7.2
MY1: CN14.25 CP6.6
MY4: CN14.22 CP7.8
MY7: CN14.19 CP7.2
MY8: CN14.18 CP8.8
MY16: CN14.10 CP10.8
NOA_STBN_0: CN6.28 U28.AA62
NOA_STBN_1: CN6.19 U28.U63
NOA_STBP_0: CN6.29 U28.AA61
NOA_STBP_1: CN6.20 U28.U62
ODD_PRSNT#: R504.1 TP95.1
OPI_COMP1: R224.2
OPI_COMP2: R223.2
PCBEEP_EC: D18.2
PCH_ACPRESENT: R134.1 R139.1 R165.1
PCH_AZ_CODEC_BITCLK: C320.2 C448.2 R529.1 U17.6
PCH_AZ_CODEC_SDIN0: R287.1
PCH_AZ_CODEC_SYNC: R532.1 U17.10
PCH_BATLOW#: R471.1 R505.1
PCH_BLON: R68.2
PCH_BLON_R: Q10.5 R67.2 R68.1 R69.2
PCH_BRIGHT: CN7.27 R551.1
PCH_INTVRMEN: R525.1 R526.2 U28.AV7
PCH_JTAG_TDO: R271.2 R303.2
PCH_JTAGX: R562.1 R571.2
PCH_RSMRST#: R510.1 R511.1 U28.AW6
PCH_SLP_LAN#: TP31.1
PCH_SLP_S0#: TP17.1
PCH_SLP_S5#: TP32.1
PCH_SLP_WLAN#: TP38.1
PCH_SPI_CLK_EC: R426.2
PCH_SPI_CS0#: U24.1
PCH_SPI_SI: R427.2 U28.AA2
PCH_SPI_SI_EC: R395.1 R428.2
PCH_SPI_SO: R430.1
PCH_SPI_SO_EC: R396.1 R429.1
PCH_SPI_SO_R: R429.2 R430.2 U24.2
PCH_SUSCLK: TP20.1
PCH_SUSPWRACK: R445.1 R453.1 R468.1 U28.AV4
PCI_PIRQA#: R184.1 U28.U6
PCI_PIRQB#: R142.1 U28.P4
PCI_PIRQC#: R141.1 U28.N4
PCI_PIRQD#: R491.1 U28.N2
PCI_PLTRST#: U9.1 U9.2
PCI_PME#: TP94.1
PCIE_IREF: R233.1 U28.B27
PCIE_LAN_WAKE#_R: Q21.1 R291.1 R593.1
PCIE_RCOMP: R232.1 U28.A27
PCIE_REQ_LAN#_R: Q25.1 R302.1 R622.1 U36.12
PCIE_RX3+_LAN: C575.2
PCIE_RX3-_LAN: C574.2
PCIE_RXN1: TP42.1
PCIE_RXP1: TP43.1 U28.F17
PCIE_TX3+: C506.1
PCIE_TX3+_LAN: C506.2
PCIE_TX3-: C497.1
PCIE_TX3-_LAN: C497.2 U36.14
PCIE_TXP1: TP104.1 U28.C31
PCLK_TPM: C110.1 R228.1 U8.21
PD#: D15.2 D16.2 R256.2 R257.2 U17.47
PEG_RX#3: U28.E6
PEG_TX3: C468.1
PEG_TX#2: C467.1
PLTRST#: R90.1 R94.1 R312.1 R335.1 R340.1 U8.16 U9.4 U36.19
PM_EXTTS#1: JDIM6.198 R121.2
PROC_DETECT: TP116.1
PROCHOT_EC: Q18.2 R105.2
PWR_DEBUG: CN6.53 R277.2
R_PEG_TX0: C476.2
R_PEG_TX1: C480.2 U28.A23
R_PEG_TX2: C463.2 U28.C21
R_PEG_TX3: C468.2
R_PEG_TX#0: C478.1
R_PEG_TX#1: C481.2 U28.B23
R_PEG_TX#2: C467.2
R_PEG_TX#3: C474.2
R_SPK+_1: C568.1 CN15.1
R_SPK-_1: C567.1 CN15.2
RAM_ID0: R472.2 R506.1 U28.AT3
RAM_ID1: R167.2 R191.1 U28.AM3
RAM_ID2: R469.2 R502.1 U28.AM2
RAM_ID3: R163.2 R188.1
REGOUT: L20.1 U36.24
RING2: CN11.28 CN11.29 Q26.3 U17.17
RSMRST#: R482.2 R511.2
RTC_X1: C437.2 R508.1 U28.AW5 Y7.1
RTC_X2: C438.2 R508.2 U28.AY5 Y7.4
SATA_IREF: R539.1
SATA_LED#: R455.2
SATA_RCOMP: R538.2
SATA_TXP0_C: C559.1
SENSEA: R304.1 U17.13
SENSOR_INT: R138.2 U7.1
SENSOR_PCH_CLK: R210.1 R444.1
SENSOR_PCH_DAT: R203.1 R442.1
SERIRQ_R: R100.2 U8.27
SIO_A20GATE: TP80.1 U25.126
SIO_EXT_SCI#: R458.1
SKU_ID0: R466.2 R497.1 U28.Y1
SM_INTRUDER#: R481.2 U28.AU6
SM_RCOMP_0: R249.2
SM_RCOMP_1: R250.1
SM_RCOMP_2: R248.2
SMB0ALERT#: R501.2 U28.AL2
SMB1ALERT#: R485.2 U28.AU4
SMB_ME1_CLK: Q14.4 R97.2 R98.2 U28.AU3
SMB_ME1_DAT: Q14.1 R91.2 R92.2
SMB_PCH_CLK: Q17.6 R123.2 U28.AP2
SMB_PCH_DAT: Q17.3 R124.2 U28.AH1
SMBALERT#: R470.1 U28.AN2
SMBCLK0: R503.2 U28.AN1
SMBDATA0: R500.2
SPD_A0: R174.2 R199.1
SPD_A1: R173.2 R198.1
SPD_A2: R172.2 R197.1
SPD_CLK_SCLK: R133.2 U10.6
SPD_CLK_SDATA: R126.2
SPI_CS0#_UR_ME: R416.2 U25.101
SPI_HOLD_IO3_ME: R418.1 R422.2 U24.7
SPI_WP_IO2_ME: R419.2 R423.2 U24.3
SRTC_RST#: C161.1 R524.2 U28.AV6
SUSACK#_R: R467.1 R468.2 U28.AK2
SUSB#: TP14.1 U28.AT4
SUSC#: TP13.1
SYS_COM_REQ: R495.1 U28.U1
SYS_PWROK: R595.1 R596.1 R598.1 R602.2 R607.1 U38.4
SYS_PWROK_R: C571.2 R602.1 R606.1 U28.AG2
TD_IREF: R541.2
TEMP_MBAT: PR140.2 PR141.1
TESTLOW_AK8: R218.2
TESTLOW_AL8: R219.2
TESTLOW_C34: R549.2
TESTLOW_C35: R550.2
THRMTRIP#: Q42.1 R627.1
TP_DC_TEST_A60: TP110.1
TP_DC_TEST_A62: TP115.1 U28.A62
TP_DC_TEST_AV1: TP24.1 U28.AV1
TP_DC_TEST_AW1: TP100.1 U28.AW1
TP_DC_TEST_AW63: TP112.1
TP_DC_TEST_AY60: TP111.1
TP_DC_TEST_B2: TP99.1
TP_PWR: C11.2 C12.2 CN7.30 CN7.31 R129.2
TP_RST#: CN7.4 R366.1
TPCLK: R611.2 R618.2
TPCLK_R: C578.2 CN17.2 R618.1
TPD_EN: CN17.8 R621.1
TPD_INT#: CN17.7 Q19.3
TPD_INT#_D: Q19.1 R159.1 U28.U7
TPDATA_R: C577.2 CN17.3 R617.1
TPM_GPIO: R95.2 U8.6
TPM_PP: R93.1 R96.1 U8.7
TPM_RST_R: R90.2 U8.9
ULT_RVSD_61: TP57.1
ULT_RVSD_62: TP54.1
ULT_RVSD_63: TP61.1
ULT_RVSD_64: TP68.1
ULT_RVSD_65: TP47.1
ULT_RVSD_66: TP44.1
ULT_RVSD_67: TP48.1
ULT_RVSD_68: TP64.1
ULT_RVSD_69: TP51.1
ULT_RVSD_70: TP52.1 U28.P61
ULT_RVSD_71: TP50.1
ULT_RVSD_72: TP62.1 U28.N61
ULT_RVSD_73: TP70.1
ULT_RVSD_74: TP69.1
ULT_RVSD_75: TP59.1
ULT_RVSD_76: TP66.1
ULT_RVSD_77: TP65.1
ULT_RVSD_78: TP60.1
ULT_RVSD_79: TP53.1
ULT_RVSD_80: TP63.1
ULT_RVSD_81: TP67.1
USB3_RXP0_R: D26.1 R332.1
USB3_TXN0_C: C370.2 R329.2
USB3_TXP0_C: C369.2
USB_BC_ON: U40.4
USB_OC0#: RP6.6 U40.5
USB_OC2#: RP6.7 U28.AH2
USBCOMP: R222.1
USBP1+_R: D25.1 R331.1
USBP1-: R330.2
USBP2+: CN11.10 U28.AT7
USBP2-: CN11.11
USBP3+: CN11.13 U28.AT10
USBP5+: R379.2
USBP5+_R: CN7.11 R379.1
USBP5-: R380.2
USBP5-_R: CN7.10 R380.1
USBP6+_R: CN7.14 R377.1
USBP6-_R: CN7.13 R378.1
USBP7+: CN11.16
USBP7-: CN11.17
VA1: PC25.2 PC26.2 PC28.1 PC136.2 PD7.2 PD11.1 PQ24.1 PQ47.1 PQ47.2 PQ47.3 PR59.1
VA2: PD12.2 PQ47.5
WK_GPIO27: R168.1 R192.1 TP33.1
WLAN#: CN8.42 TP6.1
WRST#: C139.1 D14.2 R106.1
XDP_BPM#0: CN6.41
XDP_BPM#1: CN6.42
XDP_BPM#2: TP114.1
XDP_BPM#3: TP113.1
XDP_BPM#4: TP55.1
XDP_BPM#5: TP117.1
XDP_BPM#6: TP58.1
XDP_BPM#7: TP56.1
XDP_DBRESET_N: CN6.7 R609.1 R619.1
XDP_PREQ#: U28.K62
XDP_RST_R_N: CN6.8 R312.2
XDP_TDI: CN6.3 R273.2 U16.5 U28.AD61
XDP_TMS: CN6.2 R272.2 U28.AD62
XDP_TMS_CPU: U16.8
XTAL24_IN: C490.1 R545.1 U28.A25 Y8.3
XTAL24_OUT: C489.1 R545.2 U28.B25 Y8.1
N03288: PC28.2 PQ47.4 PR59.2 PR62.1
N05670: PQ52.2
N05802: PL15.1 PR208.1
N06510: PC53.1 PR122.2
N243495: PR185.1
N6957188: PQ27.3 PR116.2
N16379436: C353.1 CN18.13
N16382763: C359.1
N16780395: PC31.1 PR64.2
N16781232: PC32.2 PU6.12
N16789516: JP8.2 PC67.2 PC69.1 PU8.1
N16789557: PC56.2 PL16.1 PU8.10 PU8.11 PU8.12
N16789582: PC62.2 PR223.1 PU8.7
N16789596: PC56.1
N16789602: PC60.1
N16789606: PR128.1 PU8.8
N16789612: PC180.1 PR223.2
N16789664: PC183.2 PU8.15
N16824795: PC73.1 PR139.1
N16853931: C305.1 TP71.1
N16853942: C547.1 TP118.1 U36.25
N16853944: TP73.1 U36.26
N16870904: PQ31.3 PR214.1
N16876480: PC130.1
N16876574: PC21.1 PR45.2
N16876576: JP7.1 PC132.2 PQ40.5
N16928869: PQ53.2 PQ53.5 PR229.1
N16928948: PQ53.6 PR220.1 PR227.2
N16991480: PC184.2 PD13.1
N17028529: PD7.1 PR127.1
N17036761: PR136.1
N17045614: PR226.2 PU17.8
N17046311: PU17.9
N17177387: PR212.2 PU17.13
N17177693: PR210.2 PU17.12
N19870274: C292.2 U30.3 U30.4 U30.10
N47340583: C294.2 U17.39
N47340589: C303.2 U17.35
N47340595: C303.1 U17.37
N47340640: C323.1 U17.34
N47340642: C346.1 U17.19
N47341180: C322.1 U17.7
N47341285: D17.1 D18.1 R299.2
N47406101: R320.2 R322.2 U18.5
N47973729: PC23.2 PR51.1
N99212489: TP46.1
N99528855: R484.1 U28.AU2
N100631500: R572.2 U33.2
N100631544: Q41.1 R542.1 R544.1
N101127130: C157.2 Q20.2 R136.1 R151.1
N101127328: Q15.3 R136.2
N101265975: Q42.2 R628.2
N101265981: Q43.1 R628.1
N102027952: C321.2 R285.1
N102027954: C321.1 R284.2
N102030206: C304.1 R274.2
N102030208: C304.2 R280.1
N102031602: C327.1 R289.2
N102031606: C327.2 R283.1
N102339557: R146.2 R149.2
N102411350: Q45.3 R636.2 R637.2 R638.2 R639.2 R640.2 R641.2 R642.2 R643.2
N102411428: D21.1 R323.2
N102411440: D19.1 R321.2
N102803185: TP82.1
N102803358: C421.1
N103592936: R598.2 R601.1 R605.1 R608.2
N104772550: C534.1 Q38.3 Q40.2 R558.1
N104772583: C535.1 Q38.2 R556.1
N106373934: PC114.2
N106374126: PC95.1 PQ35.2 PR159.1
N106374429: PC100.1 PR15.1 PR16.1 PR20.2 PR161.2
N106389737: PC22.2 PQ14.2 PR48.1 PR49.2
N106389874: PQ46.3 PR184.2
N106398707: PC165.2 PR207.1
N106398735: PL13.3 PR92.1
N106398748: PR194.2 PR195.2
N106400087: PR103.2 PR205.1 PU7.3
N106400399: PC148.2 PR197.1
N106400425: PL12.4
N106400429: PL12.3 PR74.1
N106400442: PR191.2 PR192.2
N106400512: PC35.1 PR73.2
N106400579: PC46.2 PR112.2
N106400606: PR80.1 PR87.2 PR89.1
N107805309: Q16.2 R119.2
N107846466: TP41.1
N107846467: TP36.1 U28.H8
N107846468: TP40.1
N107846469: TP35.1 U28.J8
N107945457: C9.1 D6.2 MR6.1
N107961147: TP84.1
N108094032: PC111.2 PU10.11
N108094154: PC88.2 PD9.2 PD10.1
N108094162: PC87.1 PD9.3
N108094465: PC59.1 PR123.2
N108094467: JP15.1 PC51.2 PC57.2 PC172.2 PC178.2 PC179.2 PL14.2 PR126.1
N108099073: PQ21.2 PQ28.2 PQ29.2 PQ30.3 PR118.1 PR121.2
N108099274: PQ21.3 PR56.2
N108099282: PQ29.3 PR117.2
N108100988: PU16.3
N108176553: R334.1
N108176869: CN8.22 R340.2
N108176879: CN8.51 R336.1
N108177008: CN8.47 R335.2
N108306483: C428.1 R433.1 R434.1
N108322898: C427.1 R431.1 R432.1
N108460590: TP39.1 U28.AP8
N108460599: TP37.1 U28.AR8
N108615240: R203.2 U28.F2
N108615242: R210.2 U28.F3
N108681762: TP103.1
N108784724: Q22.3 Q26.2 Q26.5 R311.1
N108784734: C345.2 Q22.2 R313.2 R316.1
N109805540: PC135.2 PQ44.2 PR183.1
N109805889: PQ45.3 PR181.2
N109805913: PQ12.3 PR44.2
N109909169: Q9.2
N110034904: TP75.1
N110214851: C398.1 R381.1
N110600321: U8.2
N996593011: TP107.1
N996593012: TP109.1
